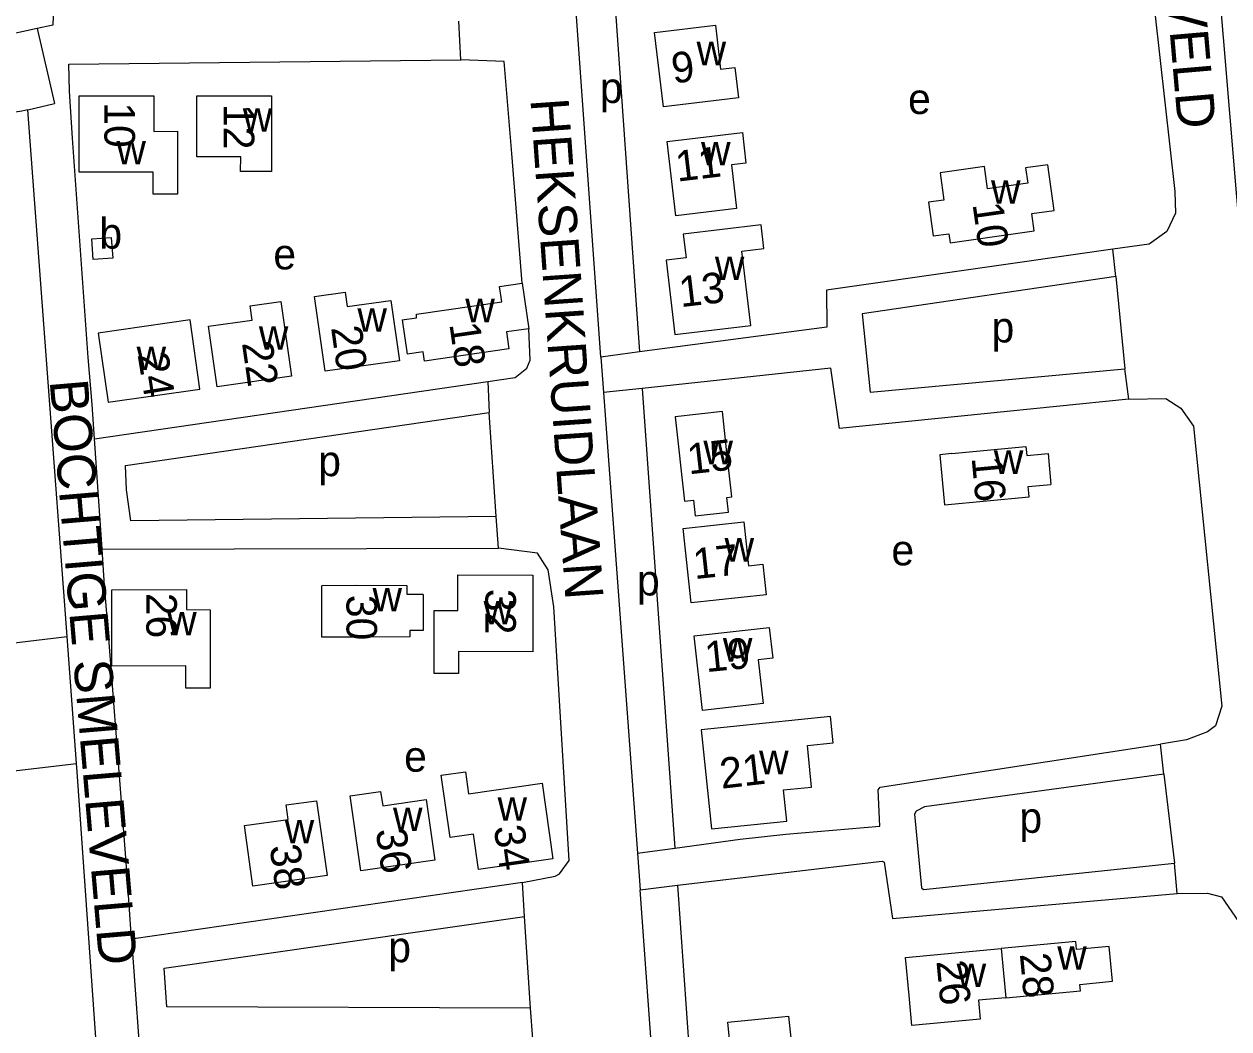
# Model space of a CAD drawing. Extents: x 162667 to 164645, y 379003 to 382150.
# Drawn here: x 162956.6 to 163114.4, y 380567.1 to 380698.6 of the extents above; entities that cross this region are included whole.
import ezdxf

# ---------------------------------------------------------------- set-up
doc = ezdxf.new("R2010")
doc.units = 0
for name, color, linetype in [('BLT_Basislijn', 7, 'Continuous'), ('BLT_Bebouwing', 7, 'Continuous'), ('BLT_Centroide', 7, 'Continuous'), ('BLT_Huisnummer', 7, 'Continuous'), ('BLT_Onderverdeling_panden', 7, 'Continuous'), ('BLT_Straatnaam', 7, 'Continuous')]:
    doc.layers.add(name, color=color, linetype=linetype)

msp = doc.modelspace()

# ---------------------------------------------------------------- linework, layer by layer
at = {"layer": 'BLT_Basislijn'}
for p, q in [((163032.99, 380714.82), (163037.19, 380655.68)), ((163032.11, 380655.01), (163027.92, 380714.18)), ((162960.84, 380710.09), (162960.36, 380698.45)), ((163013.81, 380693.92), (163013.54, 380698.94)), ((162958.3, 380698.01), (162888.68, 380682.96)), ((162960.36, 380698.45), (162958.3, 380698.01)), ((162958.3, 380698.01), (162960.6, 380688.17)), ((162957.1, 380687.38), (162960.6, 380688.17)), ((162962.24, 380618.43), (162957.1, 380687.38)), ((163099.55, 380665.57), (163099.19, 380669.11)), ((163099.55, 380665.57), (163100.75, 380653.48)), ((163032.11, 380655.01), (163032.48, 380650.37)), ((163101.28, 380649.48), (163100.75, 380653.48)), ((162965.81, 380644.29), (163017.33, 380651.82)), ((163017.33, 380651.82), (163017.5, 380647.77)), ((163032.48, 380650.37), (163036.92, 380590.08)), ((163037.53, 380650.91), (163041.83, 380590.76)), ((163018.41, 380634.16), (163017.5, 380647.77)), ((162966.81, 380629.86), (162965.81, 380644.29)), ((163018.73, 380629.99), (163018.41, 380634.16)), ((162966.81, 380629.86), (163018.73, 380629.99)), ((162935.04, 380615.2), (162962.24, 380618.43)), ((162963.48, 380601.84), (162962.24, 380618.43)), ((163105.85, 380600.43), (163105.43, 380604.34)), ((163105.85, 380600.43), (163107.23, 380588.8)), ((163041.83, 380590.76), (163050.38, 380591.92)), ((163050.38, 380591.92), (163056.35, 380592.59)), ((163036.92, 380590.08), (163041.83, 380590.76)), ((163036.92, 380590.08), (163037.27, 380585.31)), ((163107.61, 380584.83), (163107.23, 380588.8)), ((163021.88, 380586.26), (162970.65, 380578.82)), ((163022.12, 380581.82), (163021.88, 380586.26)), ((163041.61, 380524.75), (163037.27, 380585.31)), ((163042.15, 380585.89), (163046.45, 380525.55)), ((163022.92, 380569.81), (163022.12, 380581.82)), ((162970.65, 380578.82), (162971.62, 380565.58)), ((163023.21, 380565.81), (163022.92, 380569.81))]:
    msp.add_line(p, q, dxfattribs=at)
for points in [[(163116.28, 380665.57), (163112.77, 380707.3), (163114.27, 380709.01), (163147.61, 380711.21), (163185.6, 380714.88), (163208.39, 380718.9), (163230.08, 380724.48), (163246.33, 380729.8), (163260.42, 380735.06), (163271.22, 380739.44), (163282.17, 380744.37), (163282.98, 380744.48), (163295.56, 380751.32), (163300, 380754.05), (163310.75, 380759.91), (163318.6, 380764.96)], [(163095.92, 380714.84), (163098.38, 380715.05), (163101.21, 380714.31), (163103.37, 380711.77), (163107.27, 380676.68), (163107.36, 380673.84), (163106.24, 380671.45), (163103.92, 380669.79), (163099.19, 380669.11)], [(162965.81, 380644.29), (162965.5, 380648.81), (162965.01, 380654.96), (162962.93, 380683.64), (162962.55, 380689.78), (162962.47, 380693.34), (163013.81, 380693.92)], [(163019.48, 380693.69), (163013.81, 380693.92)], [(163021.84, 380664.68), (163020.47, 380681.64), (163019.48, 380693.69)], [(162957.1, 380687.38), (162956.3, 380687.19), (162955.49, 380687.07), (162955.32, 380687.07)], [(163099.19, 380669.11), (163061.67, 380663.76), (163061.7, 380658.91), (163037.19, 380655.68)], [(163099.55, 380665.57), (163066.34, 380660.68), (163067.4, 380650.4), (163100.75, 380653.48)], [(163017.33, 380651.82), (163020.89, 380652.33), (163022.42, 380653.54), (163022.88, 380654.58), (163022.7, 380658.72)], [(163037.19, 380655.68), (163032.11, 380655.01)], [(163101.28, 380649.48), (163063.39, 380645.68), (163062.24, 380653.57), (163037.53, 380650.91)], [(163037.53, 380650.91), (163032.48, 380650.37)], [(163101.28, 380649.48), (163106.13, 380649.59), (163108.06, 380648.3), (163109.74, 380645.97), (163113.46, 380609.33), (163112.62, 380606.75), (163111.58, 380605.96), (163108.84, 380604.92), (163105.43, 380604.34)], [(163018.41, 380634.16), (162970.58, 380633.57), (162970, 380637.65), (162969.88, 380640.82), (163017.5, 380647.77)], [(162970.65, 380578.82), (162970.37, 380583.36), (162969.91, 380589.47), (162967.67, 380618.77), (162967.15, 380625.12), (162966.81, 380629.86)], [(163021.88, 380586.26), (163026.16, 380587.09), (163026.73, 380587.38), (163028, 380589.13), (163025.95, 380622.33), (163025.25, 380627.16), (163023.84, 380629.34), (163018.73, 380629.99)], [(162936.69, 380610.36), (162967.4, 380520.31), (162968.51, 380517.36), (162969.4, 380517.45), (162963.56, 380600.72), (162963.48, 380601.84)], [(162943.16, 380611.13), (162944.49, 380599.58), (162963.48, 380601.84)], [(163056.35, 380592.59), (163068.64, 380593.61), (163068.46, 380598.36), (163068.71, 380598.74), (163105.43, 380604.34)], [(163105.85, 380600.43), (163074.53, 380596.14), (163073.42, 380595.6), (163073.18, 380595.18), (163074.12, 380585.56), (163074.37, 380585.34), (163107.23, 380588.8)], [(163042.15, 380585.89), (163068.95, 380589.06), (163069.21, 380588.9), (163070.32, 380581.54), (163107.61, 380584.83)], [(163037.27, 380585.31), (163042.15, 380585.89)], [(163107.61, 380584.83), (163111.58, 380584.87), (163113.41, 380584.38), (163116.12, 380580.46), (163119.23, 380546.99), (163118.93, 380543.71), (163118.3, 380542.56), (163115.74, 380540.62), (163112.09, 380540.07)], [(163022.92, 380569.81), (162975.3, 380569.97), (162974.94, 380575.04), (163022.12, 380581.82)]]:
    msp.add_lwpolyline(points, dxfattribs=at)
at = {"layer": 'BLT_Bebouwing'}
for p, q in [((163075.02, 380675.27), (163075.64, 380670.85)), ((163021.84, 380664.68), (163022.7, 380658.72)), ((163006.13, 380659.89), (163006.78, 380655.38)), ((163044.49, 380634.23), (163048.84, 380634.71)), ((163008.87, 380623.95), (163008.87, 380619.23))]:
    msp.add_line(p, q, dxfattribs=at)
for points in [[(163040.33, 380687.75), (163039.15, 380697.48), (163047.12, 380698.43), (163047.81, 380692.7), (163049.68, 380692.92), (163050.17, 380688.92)], [(162963.82, 380689.21), (162973.61, 380689.2), (162973.61, 380684.54), (162976.71, 380684.56), (162976.71, 380676.32), (162973.52, 380676.32), (162973.52, 380679.22), (162963.82, 380679.22)], [(162979.21, 380689.19), (162989.01, 380689.18), (162988.99, 380679.28), (162984.96, 380679.29), (162984.97, 380681.19), (162979.2, 380681.19)], [(163040.81, 380683.23), (163050.66, 380684.41), (163051.13, 380680.39), (163049.23, 380680.17), (163049.9, 380674.43), (163041.96, 380673.48)], [(163042.89, 380671.1), (163043.28, 380668), (163040.66, 380667.69), (163041.81, 380657.97), (163051.75, 380659.14), (163050.6, 380668.87), (163053.47, 380669.22), (163053.11, 380672.29)], [(162994.65, 380662.95), (162998.64, 380663.51), (162998.91, 380661.63), (163004.62, 380662.43), (163005.74, 380654.51), (162996.03, 380653.15)], [(162966.29, 380658.15), (162967.59, 380649.09), (162979.62, 380650.81), (162978.33, 380659.87)], [(163042.89, 380632.59), (163050.84, 380633.45), (163051.46, 380627.71), (163053.35, 380627.9), (163053.78, 380623.89), (163043.94, 380622.84)], [(163013.41, 380626.49), (163023.22, 380626.48), (163023.22, 380616.45), (163013.5, 380616.49), (163013.49, 380613.59), (163010.29, 380613.6), (163010.3, 380621.84), (163013.4, 380621.83)], [(162968.07, 380624.57), (162977.87, 380624.58), (162977.88, 380621.96), (162980.98, 380621.95), (162980.96, 380611.68), (162977.76, 380611.69), (162977.77, 380614.59), (162968.09, 380614.57)], [(163045.27, 380606.22), (163046.61, 380593.26), (163056.47, 380594.26), (163056.05, 380598.36), (163059.73, 380598.73), (163059.17, 380604.19), (163062.55, 380604.54), (163062.2, 380607.97)], [(163011.23, 380600.28), (163014.4, 380600.74), (163014.81, 380597.87), (163024.43, 380599.27), (163025.83, 380589.34), (163016.12, 380587.95), (163015.46, 380592.57), (163012.39, 380592.13)], [(162999.29, 380597.59), (163003.28, 380598.16), (163003.56, 380596.28), (163009.27, 380597.1), (163010.4, 380589.18), (163000.69, 380587.79)], [(162985.45, 380593.71), (162991.16, 380594.51), (162990.9, 380596.4), (162994.9, 380596.96), (162996.28, 380587.16), (162986.57, 380585.79)], [(163048.75, 380567.99), (163056.72, 380568.78), (163057.29, 380563.04), (163059.27, 380563.24), (163059.67, 380559.19), (163057.81, 380559.01), (163057.98, 380557.23), (163053.63, 380556.8), (163053.46, 380558.57), (163049.73, 380558.2)]]:
    msp.add_lwpolyline(points, close=True, dxfattribs=at)
for points in [[(163075.64, 380670.85), (163077.71, 380671.15), (163077.88, 380669.97), (163088.88, 380671.52), (163088.56, 380673.78), (163091.51, 380674.19), (163090.67, 380680.16), (163087.74, 380679.75), (163088.02, 380677.75), (163082.78, 380677.01), (163082.36, 380679.93), (163076.56, 380679.11), (163077.06, 380675.55), (163075.02, 380675.27)], [(162965.45, 380670.47), (162968.02, 380670.65), (162968.22, 380667.96), (162965.65, 380667.77), (162965.45, 380670.47)], [(163006.13, 380659.89), (163007.99, 380660.16), (163007.97, 380660.61), (163019.16, 380662.23), (163018.87, 380664.24), (163021.84, 380664.68)], [(162980.75, 380659.03), (162986.46, 380659.85), (162986.2, 380661.71), (162990.2, 380662.29), (162991.61, 380652.51), (162981.89, 380651.11), (162980.75, 380659.03)], [(163022.7, 380658.72), (163019.77, 380658.29), (163020.09, 380656.07), (163009.05, 380654.48), (163008.88, 380655.68), (163006.78, 380655.38)], [(163048.84, 380634.71), (163048.62, 380636.64), (163049.3, 380636.72), (163048.6, 380642.93), (163048.04, 380647.9), (163041.84, 380647.2), (163043.08, 380636.15), (163044.26, 380636.28), (163044.49, 380634.23)], [(163078.11, 380642.38), (163076.52, 380642.23), (163077.14, 380635.65), (163088.2, 380636.7)], [(163078.11, 380642.38), (163087.79, 380643.3), (163087.9, 380642.12), (163090.69, 380642.38), (163091.07, 380638.33)], [(163088.2, 380636.7), (163088.16, 380637.19), (163088.08, 380638.05), (163091.07, 380638.33)], [(163008.87, 380623.95), (163006.77, 380623.94), (163006.77, 380625.09), (163000, 380625.1), (162995.57, 380625.09)], [(163008.87, 380619.23), (163007.11, 380619.22), (163007.11, 380618.39), (163000, 380618.37), (162995.58, 380618.36), (162995.57, 380625.09)], [(163044.34, 380618.51), (163054.19, 380619.64), (163054.64, 380615.61), (163052.73, 380615.4), (163053.38, 380609.66), (163045.43, 380608.76), (163044.34, 380618.51)], [(163085.15, 380571.18), (163081.58, 380570.84), (163081.81, 380568.35), (163072.87, 380567.52), (163072.5, 380571.48), (163072.04, 380576.45), (163084.56, 380577.61)], [(163098.68, 380577.89), (163094.42, 380577.49), (163094.32, 380578.51), (163084.56, 380577.61)], [(163085.15, 380571.18), (163094.95, 380572.08), (163094.87, 380572.9), (163099.14, 380573.33), (163098.68, 380577.89)]]:
    msp.add_lwpolyline(points, dxfattribs=at)
at = {"layer": 'BLT_Onderverdeling_panden'}
msp.add_line((163084.56, 380577.61), (163085.15, 380571.18), dxfattribs=at)

# ---------------------------------------------------------------- texts
at = {"layer": 'BLT_Centroide'}
for s, p in [('w', (163044.66, 380693.19)), ('p', (163032.01, 380688.25)), ('e', (163072.36, 380686.81)), ('w', (162985.24, 380684.5)), ('w', (162968.69, 380680.22)), ('w', (163045.25, 380680.08)), ('w', (163083.22, 380675.06)), ('b', (162966.46, 380669.2)), ('e', (162989.24, 380666.48)), ('w', (163047.06, 380665.09)), ('w', (163014.38, 380659.56)), ('w', (163000.25, 380658.31)), ('p', (163083.29, 380656.92)), ('w', (162987.34, 380655.97)), ('w', (162971.33, 380653.3)), ('w', (163045.56, 380640.98)), ('p', (162995.12, 380639.42)), ('w', (163083.59, 380639.72)), ('w', (163048.33, 380628.25)), ('e', (163070.18, 380627.75)), ('p', (163036.86, 380623.81)), ('w', (163002.23, 380621.72)), ('w', (163016.76, 380620.03)), ('w', (162975.34, 380618.59)), ('w', (163048.11, 380615.17)), ('e', (163006.37, 380600.75)), ('w', (163052.85, 380600.42)), ('w', (163018.6, 380594.34)), ('w', (163004.91, 380592.97)), ('p', (163086.94, 380592.75)), ('w', (162990.73, 380591.38)), ('p', (163004.29, 380575.82)), ('w', (163091.9, 380574.84)), ('w', (163078.72, 380572.56))]:
    msp.add_text(s, height=4, dxfattribs=at).set_placement(p)
at = {"layer": 'BLT_Huisnummer'}
for s, rotation, p in [('9', 6.8095, (163041.61, 380690.8)), ('10', 270.0775, (162967.11, 380688.34)), ('12', 269.9355, (162982.75, 380688.13)), ('11', 6.6854, (163042.14, 380677.96)), ('10', 278.021, (163080.79, 380675.02)), ('13', 6.7005, (163042.59, 380661.53)), ('18', 278.2189, (163012.28, 380659.33)), ('20', 278.018, (162996.79, 380658.87)), ('22', 278.2345, (162985.12, 380656.85)), ('24', 279.2345, (162971.45, 380655.36)), ('15', 6.4097, (163043.65, 380639.65)), ('16', 275.3897, (163080.67, 380641.84)), ('17', 6.1364, (163044.41, 380625.94)), ('26', 270.1108, (162972.6, 380624.16)), ('30', 270.1108, (162998.81, 380623.89)), ('32', 269.9772, (163017, 380624.67)), ('19', 5.662, (163045.93, 380613.77)), ('21', 6.662, (163047.93, 380598.51)), ('36', 278.1301, (163002.63, 380593.12)), ('34', 278.1301, (163018.09, 380593.51)), ('38', 278.1301, (162988.73, 380590.99)), ('26', 275.2909, (163076.07, 380575.96)), ('28', 275.2827, (163086.99, 380576.9))]:
    msp.add_text(s, height=4, rotation=rotation, dxfattribs=at).set_placement(p)
at = {"layer": 'BLT_Straatnaam'}
for s, height, rotation, p in [('RENDIERVELD', 5, 274.9213, (163103.65, 380732.11)), ('HEKSENKRUIDLAAN', 5, 274.0155, (163022.9, 380688.73)), ('BOCHTIGE SMELEVELD', 4.9999, 274.8612, (162959.94, 380651.9))]:
    msp.add_text(s, height=height, rotation=rotation, dxfattribs=at).set_placement(p)

doc.saveas('drawing.dxf')
